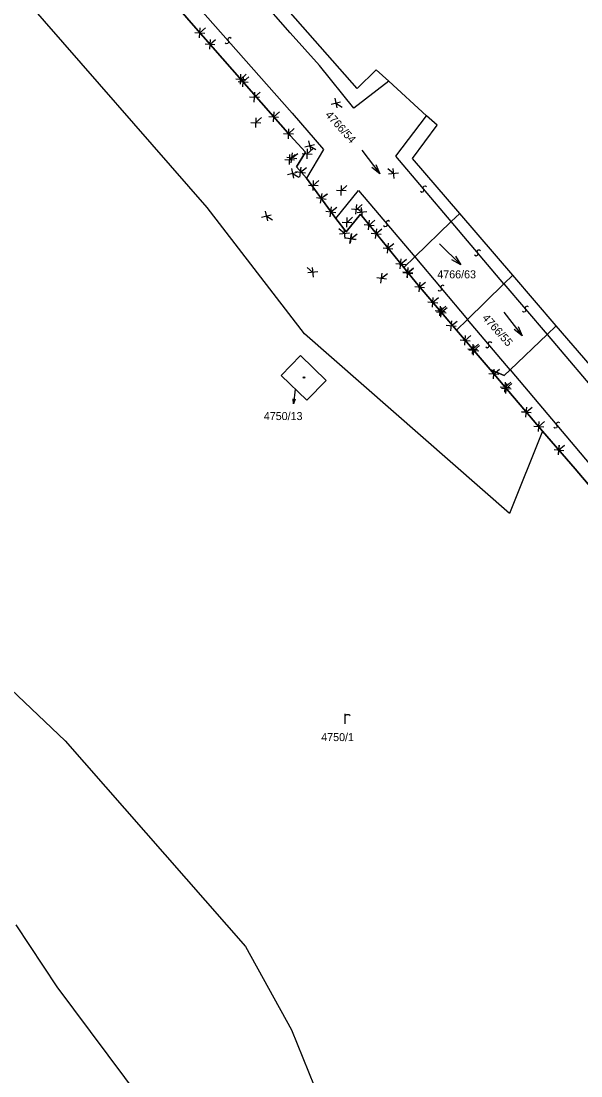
# Model space of a CAD drawing. Extents: x -266179 to -264727, y -1243225 to -1241702.
# Drawn here: x -265054 to -264942.1, y -1242530.3 to -1242319.4 of the extents above; entities that cross this region are included whole.
import ezdxf

# ---------------------------------------------------------------- set-up
doc = ezdxf.new("R2010")
doc.units = 0
for name, color, linetype in [('Vrstva 1', 7, 'Continuous'), ('Vrstva 2', 7, 'Continuous'), ('Vrstva 21', 7, 'Continuous')]:
    doc.layers.add(name, color=color, linetype=linetype)

msp = doc.modelspace()

# ---------------------------------------------------------------- linework, layer by layer
at = {"layer": 'Vrstva 1'}
for p, q in [((-265028.13, -1242310.44), (-265019.56, -1242320.32)), ((-265016.82, -1242356.72), (-265053.02, -1242315.18)), ((-264986.83, -1242332.93), (-265000.16, -1242317.8)), ((-265019.56, -1242320.32), (-265000.23, -1242342.31)), ((-264983.05, -1242329.15), (-264986.83, -1242332.93)), ((-264980.54, -1242331.42), (-264983.05, -1242329.15)), ((-264972.99, -1242338.35), (-264980.54, -1242331.42)), ((-264970.85, -1242340.24), (-264972.99, -1242338.35)), ((-264975.76, -1242346.93), (-264970.85, -1242340.24)), ((-265000.23, -1242342.31), (-264997.15, -1242345.62)), ((-264997.15, -1242345.62), (-264998.99, -1242348.6)), ((-264985.945, -1242345.211), (-264982.315, -1242349.989)), ((-264966.35, -1242357.89), (-264975.76, -1242346.93)), ((-264998.99, -1242348.6), (-264996.97, -1242350.81)), ((-264996.97, -1242350.81), (-264991.08, -1242358.9)), ((-264997.36, -1242381.96), (-265016.82, -1242356.72)), ((-264989.06, -1242361.54), (-264986.21, -1242358.05)), ((-264986.21, -1242358.05), (-264977.53, -1242368.71)), ((-264966.35, -1242357.89), (-264968.04, -1242359.53)), ((-264968.04, -1242359.53), (-264966.35, -1242357.89)), ((-264955.75, -1242370.23), (-264966.35, -1242357.89)), ((-264991.08, -1242358.9), (-264989.06, -1242361.54)), ((-264968.04, -1242359.53), (-264975.34, -1242366.59)), ((-264975.34, -1242366.59), (-264968.04, -1242359.53)), ((-264970.382, -1242363.949), (-264966.138, -1242368.191)), ((-264975.34, -1242366.59), (-264977.53, -1242368.71)), ((-264977.53, -1242368.71), (-264975.34, -1242366.59)), ((-264977.53, -1242368.71), (-264974.98, -1242371.84)), ((-264957.51, -1242371.95), (-264955.75, -1242370.23)), ((-264955.75, -1242370.23), (-264957.51, -1242371.95)), ((-264947.05, -1242380.36), (-264955.75, -1242370.23)), ((-264974.98, -1242371.84), (-264967, -1242381.2)), ((-264964.81, -1242379.07), (-264957.51, -1242371.95)), ((-264957.51, -1242371.95), (-264964.81, -1242379.07)), ((-264957.548, -1242377.637), (-264953.852, -1242382.363)), ((-264967, -1242381.2), (-264964.81, -1242379.07)), ((-264964.81, -1242379.07), (-264967, -1242381.2)), ((-264956.38, -1242417.85), (-264997.36, -1242381.96)), ((-264967, -1242381.2), (-264960.29, -1242389.06)), ((-264947.05, -1242380.36), (-264948.89, -1242382.11)), ((-264948.89, -1242382.11), (-264947.05, -1242380.36)), ((-264940.3, -1242388.21), (-264947.05, -1242380.36)), ((-264948.89, -1242382.11), (-264956.29, -1242389.17)), ((-264956.29, -1242389.17), (-264948.89, -1242382.11)), ((-265002.05, -1242390.27), (-264998.2, -1242386.3)), ((-264998.2, -1242386.3), (-264993.02, -1242391.29)), ((-264996.9, -1242395.22), (-265002.05, -1242390.27)), ((-264960.29, -1242389.06), (-264949.78, -1242401.38)), ((-264957.46, -1242390.29), (-264960.29, -1242389.06)), ((-264960.29, -1242389.06), (-264957.46, -1242390.29)), ((-264956.29, -1242389.17), (-264957.46, -1242390.29)), ((-264957.46, -1242390.29), (-264956.29, -1242389.17)), ((-264993.02, -1242391.29), (-264996.9, -1242395.22)), ((-264999.264, -1242394.99), (-264999.574, -1242395.961)), ((-264949.78, -1242401.38), (-264956.38, -1242417.85)), ((-264949.78, -1242401.38), (-264943.25, -1242408.96)), ((-264943.25, -1242408.96), (-264914.51, -1242443)), ((-265098.99, -1242412.33), (-265045.21, -1242463.31)), ((-265045.21, -1242463.31), (-265009.2, -1242504.41)), ((-265046.79, -1242512.45), (-265055.02, -1242500.08)), ((-265009.2, -1242504.41), (-264999.96, -1242521.1)), ((-265026.28, -1242539.99), (-265046.79, -1242512.45)), ((-264999.96, -1242521.1), (-264991.35, -1242542.39))]:
    msp.add_line(p, q, dxfattribs=at)
for points in [[(-264983.127, -1242348.094), (-264982.315, -1242349.989), (-264983.923, -1242348.699)], [(-264967.199, -1242366.423), (-264966.138, -1242368.191), (-264967.906, -1242367.131)], [(-264954.69, -1242380.48), (-264953.852, -1242382.363), (-264955.478, -1242381.096)], [(-264999.24, -1242392.98), (-264999.574, -1242395.961), (-264999.661, -1242394.945)], [(-264989.26, -1242459.94), (-264989.26, -1242458.67), (-264989.26, -1242457.94)], [(-264989.26, -1242458.34), (-264989.16, -1242458.21), (-264989.03, -1242458.1), (-264988.89, -1242458.05), (-264988.66, -1242458.04), (-264988.49, -1242458.07), (-264988.39, -1242458.14), (-264988.3, -1242458.24), (-264988.26, -1242458.34)]]:
    msp.add_lwpolyline(points, dxfattribs=at)
msp.add_lwpolyline([(-264997.4, -1242390.52), (-264997.31, -1242390.67), (-264997.4, -1242390.82), (-264997.58, -1242390.82), (-264997.67, -1242390.67), (-264997.58, -1242390.52)], close=True, dxfattribs=at)
at = {"layer": 'Vrstva 2'}
for p, q in [((-265000.23, -1242321.79), (-265014.24, -1242305.71)), ((-265025.44, -1242308.87), (-264999.82, -1242337.87)), ((-264994.4, -1242328.33), (-265000.23, -1242321.79)), ((-264987.5, -1242336.85), (-264994.4, -1242328.33)), ((-264980.54, -1242331.42), (-264987.5, -1242336.85)), ((-264999.82, -1242337.87), (-264993.57, -1242345.11)), ((-264979.12, -1242346.47), (-264972.99, -1242338.35)), ((-264993.57, -1242345.11), (-264996.97, -1242350.81)), ((-264968.04, -1242359.53), (-264979.12, -1242346.47)), ((-264991.08, -1242358.9), (-264986.58, -1242353.28)), ((-264986.58, -1242353.28), (-264975.34, -1242366.59)), ((-264957.51, -1242371.95), (-264968.04, -1242359.53)), ((-264975.34, -1242366.59), (-264964.81, -1242379.07)), ((-264957.51, -1242371.95), (-264948.89, -1242382.11)), ((-264956.29, -1242389.17), (-264964.81, -1242379.07)), ((-264948.89, -1242382.11), (-264916.94, -1242419.78)), ((-264956.29, -1242389.17), (-264937.64, -1242411.26))]:
    msp.add_line(p, q, dxfattribs=at)
for points in [[(-265012.035, -1242322.911), (-265012.323, -1242322.751), (-265012.62, -1242322.868), (-265012.715, -1242323.138), (-265012.534, -1242323.645), (-265012.692, -1242323.919), (-265013.001, -1242323.978), (-265013.225, -1242323.829)], [(-264974.184, -1242353.447), (-264973.9, -1242353.612), (-264973.6, -1242353.502), (-264973.5, -1242353.234), (-264973.671, -1242352.723), (-264973.507, -1242352.453), (-264973.197, -1242352.4), (-264972.976, -1242352.553)], [(-264980.355, -1242359.489), (-264980.639, -1242359.323), (-264980.939, -1242359.433), (-264981.04, -1242359.701), (-264980.87, -1242360.212), (-264981.034, -1242360.482), (-264981.344, -1242360.534), (-264981.565, -1242360.381)], [(-264963.379, -1242366.187), (-264963.095, -1242366.352), (-264962.795, -1242366.242), (-264962.695, -1242365.974), (-264962.866, -1242365.463), (-264962.702, -1242365.193), (-264962.392, -1242365.14), (-264962.171, -1242365.293)], [(-264969.469, -1242372.385), (-264969.753, -1242372.219), (-264970.054, -1242372.328), (-264970.154, -1242372.596), (-264969.985, -1242373.107), (-264970.15, -1242373.377), (-264970.459, -1242373.429), (-264970.681, -1242373.275)], [(-264952.596, -1242376.583), (-264952.88, -1242376.418), (-264953.18, -1242376.528), (-264953.28, -1242376.796), (-264953.109, -1242377.307), (-264953.273, -1242377.577), (-264953.583, -1242377.63), (-264953.804, -1242377.477)], [(-264961.155, -1242384.566), (-264960.871, -1242384.732), (-264960.571, -1242384.622), (-264960.47, -1242384.354), (-264960.64, -1242383.843), (-264960.475, -1242383.573), (-264960.166, -1242383.521), (-264959.945, -1242383.674)], [(-264946.36, -1242399.769), (-264946.644, -1242399.603), (-264946.944, -1242399.713), (-264947.045, -1242399.981), (-264946.875, -1242400.492), (-264947.039, -1242400.762), (-264947.349, -1242400.814), (-264947.57, -1242400.661)]]:
    msp.add_lwpolyline(points, dxfattribs=at)
at = {"layer": 'Vrstva 21'}
for p, q in [((-265028.13, -1242310.44), (-265019.56, -1242320.32)), ((-265019.56, -1242320.32), (-265028.13, -1242310.44)), ((-265019.56, -1242320.32), (-265000.23, -1242342.31)), ((-265000.23, -1242342.31), (-265019.56, -1242320.32)), ((-265018.373, -1242322.76), (-265018.232, -1242320.785)), ((-265018.302, -1242321.772), (-265017.169, -1242320.79)), ((-265019.29, -1242321.702), (-265017.315, -1242321.843)), ((-265017.247, -1242324.012), (-265015.271, -1242324.139)), ((-265016.323, -1242325.064), (-265016.196, -1242323.088)), ((-265016.259, -1242324.076), (-265015.133, -1242323.085)), ((-265011.122, -1242330.981), (-265009.146, -1242331.108)), ((-265010.197, -1242332.032), (-265010.07, -1242330.056)), ((-265010.134, -1242331.044), (-265009.007, -1242330.054)), ((-265009.72, -1242332.574), (-265009.593, -1242330.598)), ((-265009.656, -1242331.586), (-265008.53, -1242330.595)), ((-265010.644, -1242331.522), (-265008.668, -1242331.649)), ((-265008.357, -1242334.602), (-265006.378, -1242334.674)), ((-265007.403, -1242335.627), (-265007.332, -1242333.649)), ((-265007.367, -1242334.638), (-265006.269, -1242333.616)), ((-264991.339, -1242334.873), (-264990.883, -1242336.799)), ((-265003.594, -1242339.542), (-265003.467, -1242337.566)), ((-265003.531, -1242338.554), (-265002.404, -1242337.564)), ((-264992.074, -1242336.064), (-264990.148, -1242335.608)), ((-264991.111, -1242335.836), (-264989.834, -1242336.624)), ((-265008.078, -1242339.692), (-265006.1, -1242339.782)), ((-265007.134, -1242340.726), (-265007.044, -1242338.748)), ((-265007.089, -1242339.737), (-265005.981, -1242338.725)), ((-265004.519, -1242338.491), (-265002.543, -1242338.618)), ((-265000.593, -1242342.95), (-265000.521, -1242340.971)), ((-265000.557, -1242341.96), (-264999.459, -1242340.939)), ((-265001.546, -1242341.924), (-264999.568, -1242341.996)), ((-265000.23, -1242342.31), (-264997.15, -1242345.62)), ((-264997.15, -1242345.62), (-265000.23, -1242342.31)), ((-264996.59, -1242343.383), (-264996.133, -1242345.31)), ((-265000.344, -1242347.12), (-264999.237, -1242346.109)), ((-265000.062, -1242347.751), (-264999.754, -1242345.795)), ((-264999.908, -1242346.773), (-264998.696, -1242345.89)), ((-264997.15, -1242345.62), (-264998.99, -1242348.6)), ((-264998.99, -1242348.6), (-264997.15, -1242345.62)), ((-264997.812, -1242345.934), (-264995.834, -1242346.006)), ((-264997.325, -1242344.575), (-264995.398, -1242344.118)), ((-264996.859, -1242346.959), (-264996.787, -1242344.98)), ((-264996.823, -1242345.97), (-264995.725, -1242344.948)), ((-264996.362, -1242344.347), (-264995.085, -1242345.134)), ((-265001.333, -1242347.076), (-264999.356, -1242347.165)), ((-265000.886, -1242346.619), (-264998.93, -1242346.927)), ((-265000.389, -1242348.109), (-265000.3, -1242346.131)), ((-265000.742, -1242350.102), (-264998.815, -1242349.645)), ((-265000.007, -1242348.91), (-264999.55, -1242350.837)), ((-264999.778, -1242349.873), (-264998.502, -1242350.661)), ((-264999.157, -1242349.497), (-264997.194, -1242349.758)), ((-264998.99, -1242348.6), (-264996.97, -1242350.81)), ((-264996.97, -1242350.81), (-264998.99, -1242348.6)), ((-264998.306, -1242350.609), (-264998.045, -1242348.646)), ((-264998.175, -1242349.627), (-264996.984, -1242348.716)), ((-264979.574, -1242349.92), (-264980.736, -1242348.972)), ((-264978.589, -1242349.821), (-264980.559, -1242350.02)), ((-264979.474, -1242350.905), (-264979.674, -1242348.936)), ((-264996.97, -1242350.81), (-264991.08, -1242358.9)), ((-264991.08, -1242358.9), (-264996.97, -1242350.81)), ((-264996.604, -1242352.245), (-264994.627, -1242352.334)), ((-264995.66, -1242353.279), (-264995.571, -1242351.301)), ((-264995.616, -1242352.29), (-264994.508, -1242351.278)), ((-264990.048, -1242354.281), (-264989.977, -1242352.303)), ((-264990.013, -1242353.292), (-264988.914, -1242352.27)), ((-264994.181, -1242355.83), (-264993.873, -1242353.874)), ((-264994.177, -1242355.836), (-264993.869, -1242353.88)), ((-264994.027, -1242354.852), (-264992.814, -1242353.969)), ((-264994.023, -1242354.858), (-264992.811, -1242353.975)), ((-264991.002, -1242353.256), (-264989.023, -1242353.328)), ((-264995.005, -1242354.698), (-264993.049, -1242355.006)), ((-264995.001, -1242354.704), (-264993.045, -1242355.012)), ((-264992.229, -1242358.55), (-264991.968, -1242356.588)), ((-264992.098, -1242357.569), (-264990.907, -1242356.657)), ((-264987.102, -1242358.063), (-264986.9, -1242356.093)), ((-264987.001, -1242357.078), (-264985.837, -1242356.131)), ((-265005.992, -1242358.612), (-265004.066, -1242358.156)), ((-265005.257, -1242357.421), (-265004.801, -1242359.347)), ((-265005.029, -1242358.384), (-265003.752, -1242359.172)), ((-264993.079, -1242357.438), (-264991.117, -1242357.699)), ((-264989.06, -1242361.54), (-264986.21, -1242358.05)), ((-264986.21, -1242358.05), (-264989.06, -1242361.54)), ((-264988.916, -1242360.662), (-264988.826, -1242358.684)), ((-264988.871, -1242359.673), (-264987.764, -1242358.661)), ((-264987.985, -1242356.977), (-264986.016, -1242357.179)), ((-264985.896, -1242357.669), (-264987.058, -1242356.72)), ((-264984.911, -1242357.569), (-264986.881, -1242357.768)), ((-264986.21, -1242358.05), (-264977.53, -1242368.71)), ((-264977.53, -1242368.71), (-264986.21, -1242358.05)), ((-264985.796, -1242358.653), (-264985.996, -1242356.684)), ((-264991.08, -1242358.9), (-264989.06, -1242361.54)), ((-264989.06, -1242361.54), (-264991.08, -1242358.9)), ((-264989.86, -1242359.628), (-264987.882, -1242359.718)), ((-264985.437, -1242360.108), (-264983.468, -1242360.31)), ((-264984.554, -1242361.194), (-264984.352, -1242359.225)), ((-264984.453, -1242360.209), (-264983.289, -1242359.263)), ((-264989.374, -1242361.921), (-264990.536, -1242360.973)), ((-264988.389, -1242361.822), (-264990.359, -1242362.021)), ((-264989.274, -1242362.906), (-264989.474, -1242360.937)), ((-264989.12, -1242362.783), (-264987.164, -1242363.091)), ((-264989.023, -1242362.741), (-264987.061, -1242363.002)), ((-264988.296, -1242363.915), (-264987.988, -1242361.959)), ((-264988.172, -1242363.852), (-264987.911, -1242361.89)), ((-264988.142, -1242362.937), (-264986.929, -1242362.054)), ((-264988.042, -1242362.871), (-264986.851, -1242361.96)), ((-264984.037, -1242361.826), (-264982.067, -1242362.028)), ((-264983.153, -1242362.911), (-264982.951, -1242360.942)), ((-264983.052, -1242361.927), (-264981.889, -1242360.98)), ((-264981.673, -1242364.732), (-264979.703, -1242364.934)), ((-264980.789, -1242365.818), (-264980.587, -1242363.849)), ((-264980.688, -1242364.833), (-264979.524, -1242363.886)), ((-264978.241, -1242368.95), (-264978.039, -1242366.98)), ((-264978.14, -1242367.965), (-264976.976, -1242367.018)), ((-264995.696, -1242369.67), (-264996.858, -1242368.721)), ((-264995.596, -1242370.654), (-264995.796, -1242368.685)), ((-264979.125, -1242367.864), (-264977.155, -1242368.066)), ((-264977.53, -1242368.71), (-264974.98, -1242371.84)), ((-264974.98, -1242371.84), (-264977.53, -1242368.71)), ((-264976.84, -1242370.667), (-264976.638, -1242368.697)), ((-264976.811, -1242370.773), (-264976.654, -1242368.799)), ((-264976.739, -1242369.682), (-264975.576, -1242368.735)), ((-264976.733, -1242369.786), (-264975.591, -1242368.813)), ((-264994.711, -1242369.57), (-264996.681, -1242369.769)), ((-264982.946, -1242370.682), (-264980.983, -1242370.943)), ((-264982.095, -1242371.794), (-264981.834, -1242369.831)), ((-264981.965, -1242370.813), (-264980.773, -1242369.901)), ((-264977.724, -1242369.581), (-264975.755, -1242369.783)), ((-264977.719, -1242369.708), (-264975.746, -1242369.864)), ((-264975.355, -1242372.484), (-264973.385, -1242372.686)), ((-264974.98, -1242371.84), (-264967, -1242381.2)), ((-264967, -1242381.2), (-264974.98, -1242371.84)), ((-264974.471, -1242373.57), (-264974.269, -1242371.6)), ((-264974.37, -1242372.585), (-264973.207, -1242371.638)), ((-264972.724, -1242375.567), (-264970.75, -1242375.724)), ((-264971.815, -1242376.632), (-264971.659, -1242374.659)), ((-264971.737, -1242375.646), (-264970.596, -1242374.672)), ((-264971.23, -1242377.316), (-264969.256, -1242377.473)), ((-264971.014, -1242377.572), (-264969.041, -1242377.729)), ((-264970.321, -1242378.381), (-264970.165, -1242376.408)), ((-264970.243, -1242377.394), (-264969.102, -1242376.421)), ((-264970.106, -1242378.637), (-264969.949, -1242376.663)), ((-264970.028, -1242377.65), (-264968.886, -1242376.677)), ((-264968.158, -1242381.325), (-264967.956, -1242379.356)), ((-264968.057, -1242380.341), (-264966.894, -1242379.394)), ((-264969.042, -1242380.24), (-264967.073, -1242380.442)), ((-264967, -1242381.2), (-264960.29, -1242389.06)), ((-264960.29, -1242389.06), (-264967, -1242381.2)), ((-264966.234, -1242383.176), (-264964.261, -1242383.332)), ((-264965.326, -1242384.241), (-264965.169, -1242382.267)), ((-264965.247, -1242383.254), (-264964.106, -1242382.28)), ((-264963.83, -1242385.988), (-264963.674, -1242384.015)), ((-264963.752, -1242385.001), (-264962.611, -1242384.028)), ((-264964.739, -1242384.923), (-264962.765, -1242385.08)), ((-264964.525, -1242385.18), (-264962.551, -1242385.337)), ((-264963.616, -1242386.245), (-264963.46, -1242384.272)), ((-264963.538, -1242385.259), (-264962.397, -1242384.285)), ((-264960.502, -1242389.89), (-264958.528, -1242390.046)), ((-264960.29, -1242389.06), (-264949.78, -1242401.38)), ((-264949.78, -1242401.38), (-264960.29, -1242389.06)), ((-264959.593, -1242390.955), (-264959.437, -1242388.981)), ((-264959.515, -1242389.968), (-264958.374, -1242388.995)), ((-264957.341, -1242393.597), (-264957.184, -1242391.623)), ((-264957.262, -1242392.61), (-264956.121, -1242391.636)), ((-264957.123, -1242393.85), (-264956.966, -1242391.877)), ((-264957.045, -1242392.864), (-264955.903, -1242391.89)), ((-264958.249, -1242392.531), (-264956.276, -1242392.688)), ((-264958.032, -1242392.785), (-264956.058, -1242392.942)), ((-264953.114, -1242398.583), (-264952.967, -1242396.609)), ((-264953.104, -1242398.563), (-264952.947, -1242396.59)), ((-264953.041, -1242397.596), (-264951.904, -1242396.617)), ((-264953.025, -1242397.576), (-264951.884, -1242396.603)), ((-264954.028, -1242397.522), (-264952.053, -1242397.669)), ((-264954.012, -1242397.498), (-264952.038, -1242397.655)), ((-264951.542, -1242400.394), (-264949.568, -1242400.55)), ((-264950.633, -1242401.459), (-264950.477, -1242399.485)), ((-264950.555, -1242400.472), (-264949.414, -1242399.499)), ((-264949.78, -1242401.38), (-264943.25, -1242408.96)), ((-264943.25, -1242408.96), (-264949.78, -1242401.38)), ((-264947.504, -1242405.095), (-264945.53, -1242405.242)), ((-264947.5, -1242405.098), (-264945.526, -1242405.245)), ((-264946.59, -1242406.156), (-264946.444, -1242404.181)), ((-264946.586, -1242406.159), (-264946.44, -1242404.184)), ((-264946.517, -1242405.168), (-264945.381, -1242404.189)), ((-264946.513, -1242405.172), (-264945.377, -1242404.192)), ((-264943.25, -1242408.96), (-264914.51, -1242443)), ((-264914.51, -1242443), (-264943.25, -1242408.96))]:
    msp.add_line(p, q, dxfattribs=at)

# ---------------------------------------------------------------- texts
at = {"layer": 'Vrstva 1'}
for s, p in [('4766/54', (-264993.322, -1242338.277)), ('4766/55', (-264961.962, -1242378.867))]:
    msp.add_text(s, height=1.6, rotation=312.03281, dxfattribs=at).set_placement(p)
for s, p in [('4766/63', (-264970.833, -1242370.86)), ('4750/13', (-265005.507, -1242399.19)), ('4750/1', (-264994.033, -1242463.36))]:
    msp.add_text(s, height=1.6, dxfattribs=at).set_placement(p)

doc.saveas('drawing.dxf')
